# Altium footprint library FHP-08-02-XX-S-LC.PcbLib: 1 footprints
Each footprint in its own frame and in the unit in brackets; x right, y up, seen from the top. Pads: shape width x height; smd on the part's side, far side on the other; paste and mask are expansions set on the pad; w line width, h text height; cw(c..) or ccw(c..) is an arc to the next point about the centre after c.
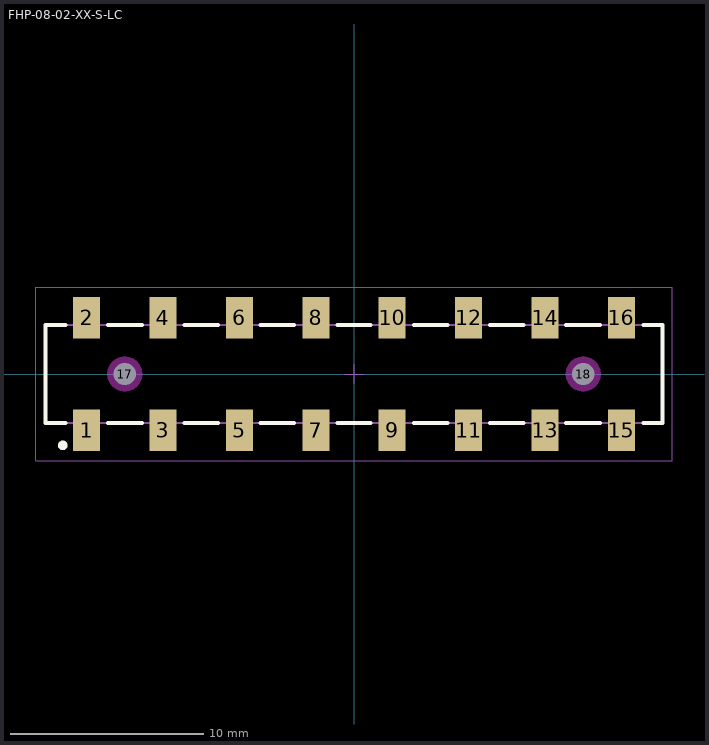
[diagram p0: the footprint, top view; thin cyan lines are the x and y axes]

## FHP-08-02-XX-S-LC [mm] "3.92mm pitch, 8 pin, power socket strip; w/locking clips"
height 9.35
pads (18):
  rect 1.4x2.15 smd mask+0: 1(-13.868,-2.921) 2(-13.868,2.921) 3(-9.906,-2.921) 4(-9.906,2.921) 5(-5.944,-2.921) 6(-5.944,2.921) 7(-1.981,-2.921) 8(-1.981,2.921) 9(1.981,-2.921) 10(1.981,2.921) 11(5.944,-2.921) 12(5.944,2.921) 13(9.906,-2.921) 14(9.906,2.921) 15(13.868,-2.921) 16(13.868,2.921)
  round 1 hole 1.15 unplated mask+0: 17(-11.887,0) 18(11.887,0)
Top Overlay:
  circle w0.25: c-15.1,-3.7 r0.125
  lines w0.2: -14.95,-2.55 -16,-2.55 -16,2.55 -14.95,2.55 ; -12.75,-2.55 -11,-2.55 ; -12.75,2.55 -11,2.55 ; -8.8,-2.55 -7.05,-2.55 ; -8.8,2.55 -7.05,2.55 ; -4.85,-2.55 -3.1,-2.55 ; -4.85,2.55 -3.1,2.55 ; -0.85,-2.55 0.85,-2.55 ; -0.85,2.55 0.85,2.55 ; 3.1,-2.55 4.85,-2.55 ; 3.1,2.55 4.85,2.55 ; 7.05,-2.55 8.8,-2.55 ; 7.05,2.55 8.8,2.55 ; 11,-2.55 12.75,-2.55 ; 11,2.55 12.75,2.55 ; 15,-2.55 16,-2.55 16,2.55 15,2.55
Keep-Out Layer:
  pour cut-out: -10.979,0 -11.01,0.235 -11.101,0.454 -11.245,0.642 -11.433,0.786 -11.652,0.877 -11.887,0.908 -12.122,0.877 -12.341,0.786 -12.529,0.642 -12.673,0.454 -12.764,0.235 -12.795,0 -12.764,-0.235 -12.673,-0.454 -12.529,-0.642 -12.341,-0.786 -12.122,-0.877 -11.887,-0.908 -11.652,-0.877 -11.433,-0.786 -11.245,-0.642 -11.101,-0.454 -11.01,-0.235
  pour cut-out: 12.795,0 12.764,0.235 12.673,0.454 12.529,0.642 12.341,0.786 12.122,0.877 11.887,0.908 11.652,0.877 11.433,0.786 11.245,0.642 11.101,0.454 11.01,0.235 10.979,0 11.01,-0.235 11.101,-0.454 11.245,-0.642 11.433,-0.786 11.652,-0.877 11.887,-0.908 12.122,-0.877 12.341,-0.786 12.529,-0.642 12.673,-0.454 12.764,-0.235
Mechanical 12:
  lines w0.001: -16,-2.55 16,-2.55 16,2.55 -16,2.55 -16,-2.55
Mechanical 13:
  lines w0.1: -16,-2.55 16,-2.55 16,2.55 -16,2.55 -16,-2.55
  text ".Designator" at 0.254,0.254 h1.52
Mechanical 15:
  lines w0.05: -0.5,0 0.5,0 ; 0,-0.5 0,0.5 ; -16.5,-4.5 16.5,-4.5 16.5,4.5 -16.5,4.5 -16.5,-4.5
